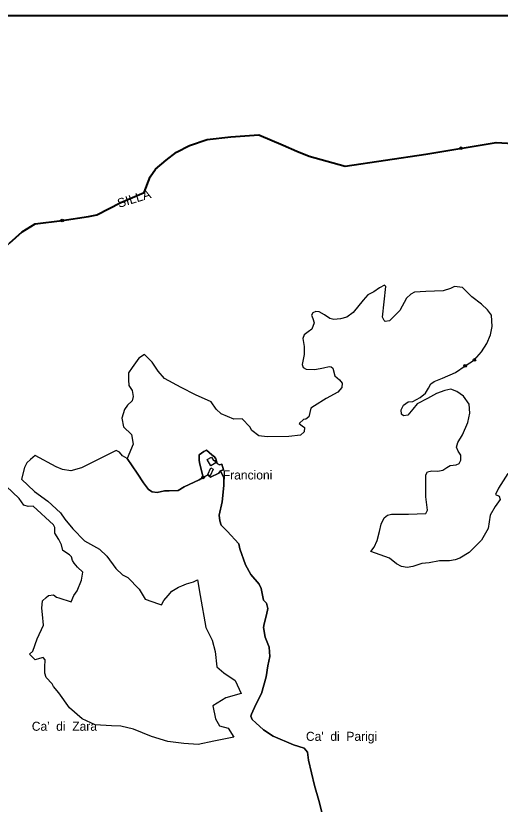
# Model space of a CAD drawing. Extents: x 645880 to 658994, y 884400 to 894744.
# Drawn here: x 656021 to 656935, y 893255 to 894744 of the extents above; entities that cross this region are included whole.
import ezdxf
from ezdxf.enums import TextEntityAlignment as Align

# ---------------------------------------------------------------- set-up
doc = ezdxf.new("R2010")
doc.units = 0
doc.header["$LTSCALE"] = 10
doc.header["$PDMODE"] = 32
doc.header["$PDSIZE"] = 5
for name, color, linetype, lineweight in [('16', 7, 'Continuous', 25), ('18', 7, 'Continuous', 25), ('3', 7, 'Continuous', 25), ('59', 7, 'Continuous', 40), ('62', 7, 'Continuous', 35)]:
    doc.layers.add(name, color=color, linetype=linetype, lineweight=lineweight)
doc.layers.add('60', color=7, linetype='Continuous')

msp = doc.modelspace()

# ---------------------------------------------------------------- linework, layer by layer
at = {"layer": '16'}
msp.add_line((656869.03, 894083.05), (656886.56, 894094.04), dxfattribs=at)
for points in [[(656886.56, 894094.04), (656899.74, 894109.38), (656910.16, 894125.02), (656917.28, 894141.75), (656920.02, 894157.11), (656918.65, 894178.51), (656911.52, 894188.93), (656900.01, 894199.08), (656881.51, 894213.01), (656864.1, 894230.9), (656849.18, 894232.6), (656841.7, 894228.66), (656827.91, 894224.6), (656794.87, 894223.54), (656773.22, 894222.35), (656766.51, 894218.29), (656758.56, 894210.88), (656745.67, 894187.57), (656726.58, 894167.65), (656717.92, 894166.86), (656715.95, 894168.44), (656713.05, 894174.68), (656719.63, 894232.55), (656716.62, 894235.57), (656707.3, 894229.91), (656697.06, 894222.42), (656685.26, 894217.3), (656676.32, 894206.76), (656657.96, 894183.72), (656645.62, 894174.94), (656634.11, 894171.65), (656621.23, 894170.55), (656613.55, 894172.2), (656603.41, 894179.33), (656593.81, 894185.09), (656587.51, 894185.64), (656581.75, 894182.89), (656579.29, 894178.51), (656581.48, 894172.2), (656584.22, 894163.97)], [(656584.22, 894163.97), (656579.83, 894152.17), (656572.7, 894147.23), (656565.02, 894141.47), (656562.56, 894134.33), (656565.02, 894119.25), (656565.02, 894104.16), (656561.73, 894085.24), (656563.1, 894079.75), (656568.94, 894076.62)], [(656408.73, 893992.4), (656399.2, 894001.29), (656389.33, 894014.73), (656360.27, 894028.11), (656333.06, 894041.81), (656301.67, 894058.93), (656289.55, 894072.76), (656278.39, 894089.75), (656263.5, 894104.13), (656252.84, 894097.27), (656240.45, 894079.98), (656233.49, 894069.95), (656233.49, 894056.82), (656234.45, 894045.56), (656240.25, 894036.18), (656242.65, 894025.29), (656240.72, 894016.84), (656231.55, 894008.98), (656225.75, 894000.54), (656220.92, 893984.5), (656223.92, 893967.96), (656239.1, 893953.54), (656242.33, 893935.26), (656231.07, 893908.2)], [(656612.17, 894081.67), (656616.02, 894081.13), (656619.57, 894078.37), (656623.41, 894063.84), (656632.04, 894056.27), (656637.23, 894050.43), (656636.36, 894041.98), (656629.01, 894033.32), (656606.94, 894021.42), (656584.66, 894007.35), (656577.74, 894002.8), (656573.84, 893987), (656568.65, 893982.24), (656564.11, 893981.59), (656555.89, 893974.23), (656561.3, 893969.9), (656565.84, 893966.43), (656564.97, 893958.42), (656558.33, 893951.95), (656536.06, 893949.28), (656495.41, 893948.91)], [(656568.94, 894076.62), (656585.31, 894075.91), (656601.76, 894079.47), (656612.17, 894081.67)], [(656798.05, 894021.14), (656778.31, 894011.47), (656770.36, 894001.04), (656760.76, 893990.07), (656752.54, 893988.43), (656748.7, 893991.72), (656748.43, 894000.22), (656752.82, 894009), (656761.59, 894014.76), (656770.13, 894015.45), (656784.34, 894022.99), (656794.21, 894031.49), (656800.24, 894041.09), (656804.62, 894049.04), (656810.93, 894053.43), (656826.28, 894059.47), (656850.94, 894070.43), (656869.03, 894083.05)], [(656739.64, 893709.45), (656726.21, 893719.88), (656691.19, 893732.49), (656697.44, 893740.46), (656703.19, 893753.35), (656707.58, 893770.36), (656710.32, 893783.8), (656716.08, 893795.87), (656722.66, 893800.8), (656730.06, 893802.72), (656761.96, 893802.72), (656778.85, 893803.55), (656794.75, 893804.1), (656798.04, 893810.4), (656795.02, 893835.91), (656794.76, 893859.5), (656794.76, 893877.33), (656798.33, 893882.82), (656806, 893885.01), (656817.79, 893883.92), (656827.11, 893886.11), (656834.54, 893890.87), (656840.75, 893894.72), (656852.05, 893896.26), (656858.08, 893898.45), (656861.1, 893905.04), (656861.1, 893914.36), (656856.16, 893921.77), (656852.6, 893929.72), (656855.34, 893938.23), (656864.38, 893952.76), (656874.25, 893976.08), (656877.81, 893993.64), (656876.44, 894010.92), (656866.3, 894025.46), (656853.69, 894034.51), (656841.9, 894038.62), (656830.94, 894036.43), (656815.31, 894030.67), (656798.05, 894021.14)], [(656495.41, 893948.91), (656479.79, 893950.82), (656466.36, 893960.69), (656462.52, 893968.1), (656448.1, 893982.72), (656432.39, 893982.25), (656408.73, 893992.4)], [(656124.63, 893884.93), (656108.64, 893887.44), (656097.08, 893892.02), (656057.39, 893913.5), (656048.61, 893906.09)], [(656374.6, 893872.48), (656366.72, 893868.02), (656338.69, 893854.4), (656327.14, 893847.8), (656310.24, 893846.98), (656301.58, 893846.98), (656287.56, 893844.09), (656278.08, 893845.33), (656271.48, 893849.45), (656261.59, 893862.24), (656249.63, 893880.39), (656231.07, 893908.2), (656222.38, 893913.22), (656216.35, 893920.08), (656210.03, 893923.23), (656144.67, 893890.15), (656124.63, 893884.93)], [(656231.07, 893908.2), (656249.63, 893880.39), (656261.59, 893862.24), (656271.48, 893849.45), (656278.08, 893845.33), (656287.56, 893844.09), (656301.58, 893846.98), (656310.24, 893846.98), (656327.14, 893847.8), (656338.69, 893854.4), (656366.72, 893868.02), (656374.6, 893872.48), (656371.55, 893885.56), (656368.17, 893897.6), (656366.7, 893904.14), (656367.12, 893914.7), (656375.98, 893921.04), (656381.05, 893923.57), (656390.75, 893914.7), (656395.82, 893910.9), (656398.14, 893907.73), (656400.67, 893898.86), (656405.31, 893896.12), (656409.53, 893897.6), (656412.7, 893886.62), (656407.42, 893884.5)], [(656130.02, 893649.21), (656136.6, 893658.13), (656144.57, 893678.46), (656147.47, 893693.7), (656137.32, 893703.13), (656130.8, 893710.39), (656127.9, 893715.47), (656125.73, 893722.73), (656122.1, 893726.36), (656109.74, 893734.54), (656106.88, 893745.23), (656101.8, 893755.39), (656094.55, 893767), (656094.55, 893777.88), (656091.65, 893782.96), (656053.77, 893818.36), (656044.01, 893817.61), (656036.12, 893820.24), (656027.23, 893832.73), (655952.79, 893902.58)], [(656048.61, 893906.09), (656041.49, 893899.79), (656037.1, 893891.01), (656031.75, 893869.17), (656056.15, 893845.53), (656081.34, 893827.41), (656104.85, 893805.38), (656113.5, 893793.56), (656128.46, 893775.44), (656150.5, 893752.59), (656178.83, 893736.83), (656192.9, 893723.54), (656209.43, 893700.69), (656221.94, 893688.2), (656232.17, 893683.48), (656253.98, 893661.23), (656265.23, 893642.5), (656290.41, 893633.83), (656295.6, 893631.55), (656300.43, 893639.76), (656308.16, 893649.61), (656315.66, 893657.34), (656327.74, 893664.85), (656334.27, 893667.89), (656342.73, 893671.41), (656356.26, 893675.4), (656363.74, 893679.14), (656368.61, 893649.57), (656379.48, 893589.33), (656391.81, 893565.37), (656396.89, 893543.6), (656400.42, 893514.93), (656413.47, 893503.32), (656435.23, 893488.8), (656446.1, 893464.12), (656417.1, 893456.14), (656392.96, 893441.33)], [(656407.42, 893884.5), (656403.84, 893880.28), (656388.27, 893873.08), (656383.55, 893877.02), (656374.6, 893872.48)], [(656407.42, 893884.5), (656413.29, 893871.84), (656413.29, 893857.15), (656410.54, 893825.95), (656405.03, 893801.16), (656405.95, 893790.15), (656408.7, 893781.89), (656419.71, 893770.87), (656441.73, 893747.01), (656443.56, 893737.83), (656454.57, 893707.54), (656464.66, 893689.18), (656480.25, 893670.83), (656483.92, 893662.57), (656488.51, 893640.54), (656494.01, 893635.03), (656496.77, 893624.93), (656494.25, 893612.82), (656489.58, 893596.23), (656488.55, 893588.96), (656491.66, 893570.81), (656498.91, 893551.62), (656500.47, 893533.99), (656496.32, 893516.36), (656493.73, 893496.13), (656484.92, 893464.5), (656474.03, 893443.75), (656465.74, 893425.6), (656464.7, 893421.45), (656467.29, 893415.23), (656474.03, 893409.01), (656488.54, 893396.04), (656506.68, 893384.11), (656545.04, 893367.52), (656565.16, 893361.2), (656571.75, 893353.87), (656573.21, 893338.48), (656584.93, 893290.84), (656592.99, 893262.26), (656606.17, 893210.23)], [(656606.17, 893210.23), (656592.99, 893262.26), (656584.93, 893290.84), (656573.21, 893338.48), (656571.75, 893353.87), (656565.16, 893361.2), (656545.04, 893367.52), (656506.68, 893384.11), (656488.54, 893396.04), (656474.03, 893409.01), (656467.29, 893415.23), (656464.7, 893421.45), (656465.74, 893425.6), (656474.03, 893443.75), (656484.92, 893464.5), (656493.73, 893496.13), (656496.32, 893516.36), (656500.47, 893533.99), (656498.91, 893551.62), (656491.66, 893570.81), (656488.55, 893588.96), (656489.58, 893596.23), (656494.25, 893612.82), (656496.77, 893624.93), (656494.01, 893635.03), (656488.51, 893640.54), (656483.92, 893662.57), (656480.25, 893670.83), (656464.66, 893689.18), (656454.57, 893707.54), (656443.56, 893737.83), (656441.73, 893747.01), (656419.71, 893770.87), (656408.7, 893781.89), (656405.95, 893790.15), (656405.03, 893801.16), (656410.54, 893825.95), (656413.29, 893857.15), (656413.29, 893871.84), (656407.42, 893884.5)], [(656949.6, 893879.77), (656932.32, 893852.34), (656926.56, 893840.27), (656933.14, 893836.98), (656935.06, 893830.39), (656925.74, 893817.23), (656916.42, 893801.32), (656912.4, 893775.96), (656900.32, 893753.92), (656876.63, 893730.47), (656859.23, 893719.69), (656850.38, 893716.86), (656839.42, 893714.94), (656821.05, 893714.94), (656801.04, 893710.83), (656787.34, 893709.73), (656770.62, 893703.97), (656759.93, 893702.05)], [(656759.93, 893702.05), (656748.96, 893704.24), (656739.64, 893709.45)], [(656392.96, 893441.33), (656397.85, 893416.52), (656405.5, 893403.15), (656421.89, 893399.23), (656432.33, 893382.1), (656394.84, 893374.42), (656365.17, 893368.41), (656337.73, 893369.83), (656307.76, 893373.58), (656276.82, 893382.96), (656242.99, 893397.03), (656218.82, 893402.66), (656201.42, 893403.6), (656170.48, 893405.47), (656146.31, 893416.73), (656122.14, 893437.36), (656101.84, 893465.5), (656092, 893477.54), (656089.42, 893482.96), (656078.19, 893494.7), (656075.64, 893502.56), (656075.64, 893514.17), (656076.31, 893528.16), (656072.18, 893532.67), (656065.79, 893530.41), (656057.53, 893528.16), (656046.68, 893538.67), (656053.21, 893544.48), (656061.28, 893567.64), (656072.93, 893593.2), (656071.33, 893613.42), (656069.88, 893625.76), (656071.42, 893639.06), (656078.18, 893645.82), (656082.69, 893649.21), (656092.08, 893650.71), (656097.45, 893646.52), (656101.8, 893645.07), (656125.14, 893637.55), (656130.02, 893649.21)]]:
    msp.add_lwpolyline(points, dxfattribs=at)
for p in [(656886.56, 894094.04), (656869.03, 894083.05), (656374.6, 893872.48)]:
    msp.add_point(p, dxfattribs=at)
at = {"layer": '18'}
msp.add_line((656869.03, 894083.05), (656886.56, 894094.04), dxfattribs=at)
for points in [[(656108.11, 894357.43), (656133.1, 894361.27), (656158.09, 894365.12), (656173.95, 894368.2), (656219.17, 894391.29), (656241.17, 894400.81), (656263.18, 894410.34), (656274.28, 894439.59), (656284.6, 894454.21), (656304.43, 894471.14), (656324.26, 894486.53), (656348.85, 894498.84), (656365.51, 894504.61), (656382.17, 894510.39), (656426.6, 894515), (656453.17, 894516.93), (656479.75, 894518.85), (656502.75, 894509.23), (656525.76, 894499.61), (656551.08, 894488.15), (656574.4, 894478.55), (656608.67, 894469.29), (656642.95, 894460.04), (656718.91, 894471.35), (656794.88, 894482.66), (656861.31, 894493.63)], [(656861.31, 894493.63), (656927.73, 894504.6), (656981.21, 894501.51), (657034.69, 894498.43)], [(655978, 893976.34), (655976.52, 893991.12), (655973.22, 894006.2), (655950.75, 894045.98), (655938.16, 894062.77), (655929.09, 894075.33), (655933.22, 894085.75), (655933.95, 894094.46), (655923.34, 894114.83), (655877.83, 894089.86), (655860.84, 894077.25), (655852.29, 894065.91), (655859.83, 894095.54), (655867.77, 894141.72), (655867.77, 894155.57), (655885.99, 894189.66), (655905.82, 894226.6), (655938.35, 894247.38), (656008.95, 894314.33), (656032.75, 894335.88), (656057.34, 894351.27), (656108.11, 894357.43)], [(656886.56, 894094.04), (656899.74, 894109.38), (656910.16, 894125.02), (656917.28, 894141.75), (656920.02, 894157.11), (656918.65, 894178.51), (656911.52, 894188.93), (656900.01, 894199.08), (656881.51, 894213.01), (656864.1, 894230.9), (656849.18, 894232.6), (656841.7, 894228.66), (656827.91, 894224.6), (656794.87, 894223.54), (656773.22, 894222.35), (656766.51, 894218.29), (656758.56, 894210.88), (656745.67, 894187.57), (656726.58, 894167.65), (656717.92, 894166.86), (656715.95, 894168.44), (656713.05, 894174.68), (656719.63, 894232.55), (656716.62, 894235.57), (656707.3, 894229.91), (656697.06, 894222.42), (656685.26, 894217.3), (656676.32, 894206.76), (656657.96, 894183.72), (656645.62, 894174.94), (656634.11, 894171.65), (656621.23, 894170.55), (656613.55, 894172.2), (656603.41, 894179.33), (656593.81, 894185.09), (656587.51, 894185.64), (656581.75, 894182.89), (656579.29, 894178.51), (656581.48, 894172.2), (656584.22, 894163.97)], [(656584.22, 894163.97), (656579.83, 894152.17), (656572.7, 894147.23), (656565.02, 894141.47), (656562.56, 894134.33), (656565.02, 894119.25), (656565.02, 894104.16), (656561.73, 894085.24), (656563.1, 894079.75), (656568.94, 894076.62)], [(656408.73, 893992.4), (656399.2, 894001.29), (656389.33, 894014.73), (656360.27, 894028.11), (656333.06, 894041.81), (656301.67, 894058.93), (656289.55, 894072.76), (656278.39, 894089.75), (656263.5, 894104.13), (656252.84, 894097.27), (656240.45, 894079.98), (656233.49, 894069.95), (656233.49, 894056.82), (656234.45, 894045.56), (656240.25, 894036.18), (656242.65, 894025.29), (656240.72, 894016.84), (656231.55, 894008.98), (656225.75, 894000.54), (656220.92, 893984.5), (656223.92, 893967.96), (656239.1, 893953.54), (656242.33, 893935.26), (656231.07, 893908.2), (656222.38, 893913.22), (656216.35, 893920.08), (656210.03, 893923.23), (656144.67, 893890.15), (656124.63, 893884.93)], [(656612.17, 894081.67), (656616.02, 894081.13), (656619.57, 894078.37), (656623.41, 894063.84), (656632.04, 894056.27), (656637.23, 894050.43), (656636.36, 894041.98), (656629.01, 894033.32), (656606.94, 894021.42), (656584.66, 894007.35), (656577.74, 894002.8), (656573.84, 893987), (656568.65, 893982.24), (656564.11, 893981.59), (656555.89, 893974.23), (656561.3, 893969.9), (656565.84, 893966.43), (656564.97, 893958.42), (656558.33, 893951.95), (656536.06, 893949.28), (656495.41, 893948.91)], [(656568.94, 894076.62), (656585.31, 894075.91), (656601.76, 894079.47), (656612.17, 894081.67)], [(656804.62, 894049.04), (656810.93, 894053.43), (656826.28, 894059.47), (656850.94, 894070.43), (656869.03, 894083.05)], [(656798.04, 893810.4), (656795.02, 893835.91), (656794.76, 893859.5), (656794.76, 893877.33), (656798.33, 893882.82), (656806, 893885.01), (656817.79, 893883.92), (656827.11, 893886.11), (656834.54, 893890.87), (656840.75, 893894.72), (656852.05, 893896.26), (656858.08, 893898.45), (656861.1, 893905.04), (656861.1, 893914.36), (656856.16, 893921.77), (656852.6, 893929.72), (656855.34, 893938.23), (656864.38, 893952.76), (656874.25, 893976.08), (656877.81, 893993.64), (656876.44, 894010.92), (656866.3, 894025.46), (656853.69, 894034.51), (656841.9, 894038.62), (656830.94, 894036.43), (656815.31, 894030.67), (656798.05, 894021.14), (656778.31, 894011.47), (656770.36, 894001.04), (656760.76, 893990.07), (656752.54, 893988.43), (656748.7, 893991.72), (656748.43, 894000.22), (656752.82, 894009), (656761.59, 894014.76), (656770.13, 894015.45), (656784.34, 894022.99), (656794.21, 894031.49), (656800.24, 894041.09), (656804.62, 894049.04)], [(656495.41, 893948.91), (656479.79, 893950.82), (656466.36, 893960.69), (656462.52, 893968.1), (656448.1, 893982.72), (656432.39, 893982.25), (656408.73, 893992.4)], [(656124.63, 893884.93), (656108.64, 893887.44), (656097.08, 893892.02), (656057.39, 893913.5), (656048.61, 893906.09)], [(656130.02, 893649.21), (656136.6, 893658.13), (656144.57, 893678.46), (656147.47, 893693.7), (656137.32, 893703.13), (656130.8, 893710.39), (656127.9, 893715.47), (656125.73, 893722.73), (656122.1, 893726.36), (656109.74, 893734.54), (656106.88, 893745.23), (656101.8, 893755.39), (656094.55, 893767), (656094.55, 893777.88), (656091.65, 893782.96), (656053.77, 893818.36), (656044.01, 893817.61), (656036.12, 893820.24), (656027.23, 893832.73), (655952.79, 893902.58)], [(656048.61, 893906.09), (656041.49, 893899.79), (656037.1, 893891.01), (656031.75, 893869.17), (656056.15, 893845.53), (656081.34, 893827.41), (656104.85, 893805.38), (656113.5, 893793.56), (656128.46, 893775.44), (656150.5, 893752.59), (656178.83, 893736.83), (656192.9, 893723.54), (656209.43, 893700.69), (656221.94, 893688.2), (656232.17, 893683.48), (656253.98, 893661.23), (656265.23, 893642.5), (656290.41, 893633.83), (656295.6, 893631.55), (656300.43, 893639.76), (656308.16, 893649.61), (656315.66, 893657.34), (656327.74, 893664.85), (656334.27, 893667.89), (656342.73, 893671.41), (656356.26, 893675.4), (656363.74, 893679.14), (656368.61, 893649.57), (656379.48, 893589.33), (656391.81, 893565.37), (656396.89, 893543.6), (656400.42, 893514.93), (656413.47, 893503.32), (656435.23, 893488.8), (656446.1, 893464.12), (656417.1, 893456.14), (656392.96, 893441.33)], [(656949.6, 893879.77), (656932.32, 893852.34), (656926.56, 893840.27), (656933.14, 893836.98), (656935.06, 893830.39), (656925.74, 893817.23), (656916.42, 893801.32), (656912.4, 893775.96), (656900.32, 893753.92), (656876.63, 893730.47), (656859.23, 893719.69), (656850.38, 893716.86), (656839.42, 893714.94), (656821.05, 893714.94), (656801.04, 893710.83), (656787.34, 893709.73), (656770.62, 893703.97), (656759.93, 893702.05)], [(656739.64, 893709.45), (656726.21, 893719.88), (656691.19, 893732.49), (656697.44, 893740.46), (656703.19, 893753.35), (656707.58, 893770.36), (656710.32, 893783.8), (656716.08, 893795.87), (656722.66, 893800.8), (656730.06, 893802.72), (656761.96, 893802.72), (656778.85, 893803.55), (656794.75, 893804.1), (656798.04, 893810.4)], [(656759.93, 893702.05), (656748.96, 893704.24), (656739.64, 893709.45)], [(656392.96, 893441.33), (656397.85, 893416.52), (656405.5, 893403.15), (656421.89, 893399.23), (656432.33, 893382.1), (656394.84, 893374.42), (656365.17, 893368.41), (656337.73, 893369.83), (656307.76, 893373.58), (656276.82, 893382.96), (656242.99, 893397.03), (656218.82, 893402.66), (656201.42, 893403.6), (656170.48, 893405.47), (656146.31, 893416.73), (656122.14, 893437.36), (656101.84, 893465.5), (656092, 893477.54), (656089.42, 893482.96), (656078.19, 893494.7), (656075.64, 893502.56), (656075.64, 893514.17), (656076.31, 893528.16), (656072.18, 893532.67), (656065.79, 893530.41), (656057.53, 893528.16), (656046.68, 893538.67), (656053.21, 893544.48), (656061.28, 893567.64), (656072.93, 893593.2), (656071.33, 893613.42), (656069.88, 893625.76), (656071.42, 893639.06), (656078.18, 893645.82), (656082.69, 893649.21), (656092.08, 893650.71), (656097.45, 893646.52), (656101.8, 893645.07), (656125.14, 893637.55), (656130.02, 893649.21)]]:
    msp.add_lwpolyline(points, dxfattribs=at)
for p in [(656861.31, 894493.63), (656108.11, 894357.43), (656886.56, 894094.04), (656869.03, 894083.05)]:
    msp.add_point(p, dxfattribs=at)
at = {"layer": '3'}
for points in [[(656403.84, 893880.28), (656407.42, 893884.5), (656412.7, 893886.62), (656409.53, 893897.6), (656405.31, 893896.12), (656400.67, 893898.86), (656398.14, 893907.73), (656395.82, 893910.9), (656390.75, 893914.7), (656381.05, 893923.57), (656375.98, 893921.04), (656367.12, 893914.7), (656366.7, 893904.14), (656368.17, 893897.6), (656371.55, 893885.56), (656374.6, 893872.48), (656383.55, 893877.02), (656388.27, 893873.08)], [(656382.16, 893906.12), (656390.36, 893910.88), (656394.25, 893904.54), (656395.45, 893905.13), (656398.21, 893899.78), (656388.96, 893893.96)], [(656383.23, 893878.15), (656388.73, 893890.2), (656393.41, 893887.73), (656387.68, 893875.61)]]:
    msp.add_lwpolyline(points, close=True, dxfattribs=at)
at = {"layer": '59'}
msp.add_lwpolyline([(656008.92, 894314.3), (656032.72, 894335.85), (656057.31, 894351.24), (656108.08, 894357.4), (656158.06, 894365.09), (656173.92, 894368.17), (656219.14, 894391.26), (656263.15, 894410.31), (656274.25, 894439.56), (656284.57, 894454.18), (656304.4, 894471.11), (656324.23, 894486.5), (656348.82, 894498.81), (656382.14, 894510.36), (656426.57, 894514.97), (656479.72, 894518.82), (656525.73, 894499.58), (656551.05, 894488.12), (656574.37, 894478.52), (656642.92, 894460.01), (656794.85, 894482.63), (656927.7, 894504.57), (657034.66, 894498.4)], dxfattribs=at)
at = {"layer": '62', "lineweight": 40}
msp.add_lwpolyline([(650022.35, 889003.81), (658994.16, 889003.81), (658994.16, 894743.81), (650022.35, 894743.81)], close=True, dxfattribs=at)
msp.add_lwpolyline([(650022.35, 889003.81), (658994.16, 889003.81), (658994.16, 894743.81), (650022.35, 894743.81)], close=True, dxfattribs=at)

# ---------------------------------------------------------------- texts
at = {"layer": '60', "width": 1.05}
msp.add_text('SILLA', height=17, rotation=17.204, dxfattribs=at).set_placement((656246.52, 894390.62), align=Align.CENTER)
at = {"layer": '60'}
for s, p in [('Francioni', (656458.37, 893868.42)), ("Ca'  di  Zara", (656112.51, 893394.09)), ("Ca'  di  Parigi", (656635.8, 893375.07))]:
    msp.add_text(s, height=17, dxfattribs=at).set_placement(p, align=Align.CENTER)

doc.saveas('drawing.dxf')
